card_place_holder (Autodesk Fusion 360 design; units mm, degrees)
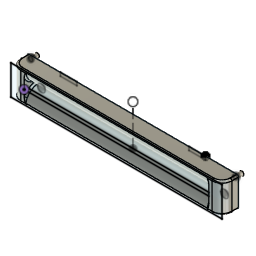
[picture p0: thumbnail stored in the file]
sketch "Sketch1" plane through (0, 0, 0) normal (0, 1, 0) x axis (1, 0, 0)
  line L1 (56, 0) -> (0, 0)
  line L2 (56, -1) -> (56, 0)
  line L3 (0, -1) -> (56, -1)
  line L4 (0, 0) -> (0, -1)
  line L5 (-4, -5) -> (60, -5)
  line L6 (-4, 4) -> (-4, -5)
  line L7 (60, 4) -> (-4, 4)
  line L8 (60, -5) -> (60, 4)
  point P1 (0, 0)
  point P2 (0, 0)
  point P3 (56, 0)
  point P5 (0, -1)
  horizontal L1
  vertical L2
  horizontal L3
  vertical L4
  coincident P1 P2
  dimension "d1" distance P2 P3 = 56
  dimension "d2" distance P2 P5 = 1
  dimension "d3" = -4
extrude "Extrude1" new body sketch "Sketch1" along normal blind 8
fillet "Fillet1" radius 4
fillet "Fillet2" radius 3
fillet "Fillet3" radius 0.5
fillet "Fillet4" radius 0.5
extrude "Extrude2" cut of existing geometry blind -3
fillet "Fillet5" radius 0.5
fillet "Fillet6" radius 0.5
fillet "Fillet7" radius 0.5
sketch "Sketch2" plane through (0, 5, 0) normal (0, 1, 0) x axis (-1, 0, 0)
  line L1 (-55.5, 0) -> (-0.5, 0)
  line L2 (-0.5, 1) -> (-55.5, 1)
  line L3 (-59.5, 5) -> (3.5, 5)
  line L4 (-60, -3.5) -> (-60, 4.5)
  line L5 (3.5, -4) -> (-59.5, -4)
  line L6 (4, 4.5) -> (4, -3.5)
  line L7 (-28, 8.2756) -> (-28, -4)
  line L8 (-28, 8.2756) -> (-28, -4)
  line L9 (-45, 5) -> (-50, 5)
  line L10 (-45, 4) -> (-45, 5)
  line L11 (-50, 4) -> (-45, 4)
  line L12 (-50, 5) -> (-50, 4)
  line L13 (-6, 4) -> (-11, 4)
  line L14 (-11, 4) -> (-11, 5)
  line L15 (-11, 5) -> (-6, 5)
  line L16 (-6, 5) -> (-6, 4)
  line L17 (-28, 8.2756) -> (-28, -4)
  arc A1 centre (-0.5, 0.5) radius 0.5 clockwise from (-0.5, 1) to (-0.5, 0)
  arc A2 centre (-55.5, 0.5) radius 0.5 clockwise from (-55.5, 0) to (-55.5, 1)
  arc A3 centre (3.5, 4.5) radius 0.5 clockwise from (3.5, 5) to (4, 4.5)
  arc A4 centre (-59.5, 4.5) radius 0.5 clockwise from (-60, 4.5) to (-59.5, 5)
  arc A5 centre (-59.5, -3.5) radius 0.5 clockwise from (-59.5, -4) to (-60, -3.5)
  arc A6 centre (3.5, -3.5) radius 0.5 clockwise from (4, -3.5) to (3.5, -4)
  circle C1 centre (-55.75, -2) radius 1.125
  circle C2 centre (-0.25, -2) radius 1.125
  circle C3 centre (-59, 4) radius 0.625
  circle C4 centre (3, 4) radius 0.625
  point P21 (-28, -4)
  point P23 (-28, -4)
  point P22 (-28, 8.2756)
  point P24 (-28, 8.2756)
  point P26 (-50, 5)
  point P33 (-6, 5)
  point P27 (-45, 5)
  point P32 (-11, 5)
  point P28 (-45, 4)
  point P30 (-11, 4)
  point P29 (-50, 4)
  point P31 (-6, 4)
  point P36 (-28, -4)
  point P37 (-28, 8.2756)
  point P34 (-59, 4)
  point P35 (3, 4)
  point P20 (-55.75, -2)
  point P25 (-0.25, -2)
  midpoint L5 P21
  perpendicular L2 L7
  symmetric C1 L7 C2
  symmetric P21 L7 P23
  symmetric P22 L7 P24
  horizontal L9
  vertical L10
  horizontal L11
  vertical L12
  coincident L3 P26
  symmetric L8 P26 P33
  symmetric L8 P27 P32
  symmetric L8 P28 P30
  symmetric L8 P29 P31
  symmetric P21 L7 P36
  symmetric P22 L7 P37
  symmetric L7 P34 P35
  symmetric C3 L17 C4
  dimension "d22" diameter C1 = 2.25
  dimension "d28" distance P20 P25 = 55.5
  dimension "d29" distance P26 P27 = 5
  dimension "d30" distance P26 P29 = 1
  dimension "d31" distance L7 L10 = 17
  dimension "d34" diameter C3 = 1.25
  dimension "d35" distance L4 P34 = 1
  dimension "d36" distance L3 P34 = 1
  dimension "d39" distance L1 P20 = 2
extrude "Extrude3" add sketch "Sketch2" profile of C1 C2 along normal blind 2
extrude "Extrude5" add sketch "Sketch2" profile of C3 C4 along normal blind 2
